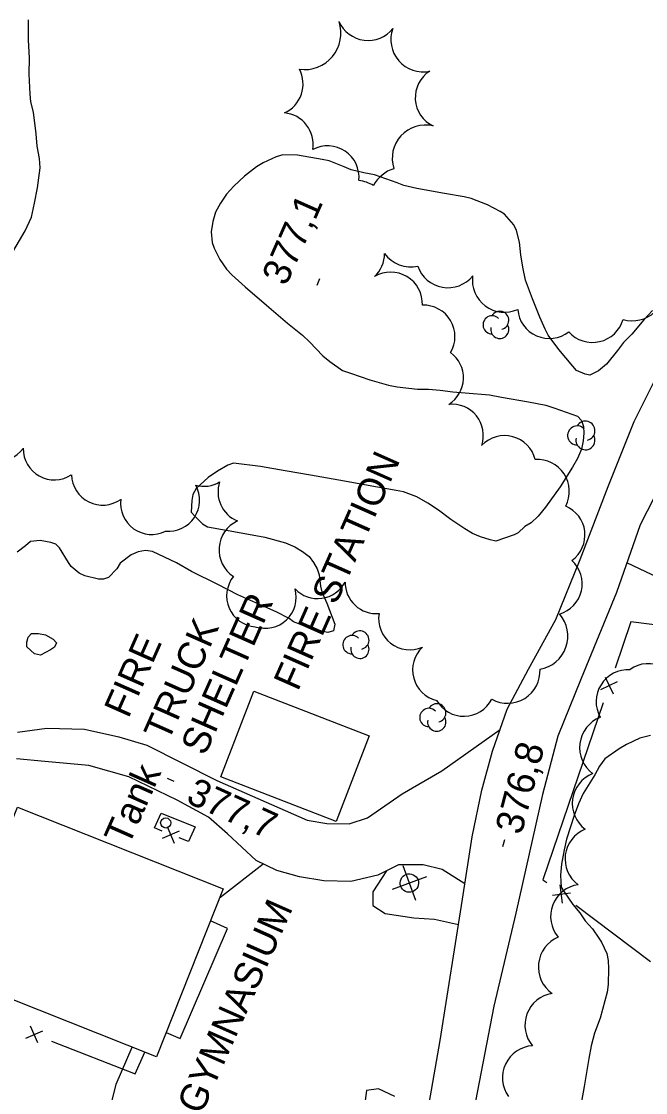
# Model space of a CAD drawing. Extents: x 287698 to 290158, y 5234163 to 5237182.
# Drawn here: x 288888.3 to 288956.3, y 5234921.6 to 5235038.1 of the extents above; entities that cross this region are included whole.
import ezdxf

# ---------------------------------------------------------------- set-up
doc = ezdxf.new("R2010")
doc.units = 0
for name, color, linetype in [('Niveau 19', 7, 'Continuous'), ('Niveau 2', 7, 'Continuous'), ('Niveau 21', 7, 'Continuous'), ('Niveau 3', 7, 'Continuous'), ('Niveau 31', 7, 'Continuous'), ('Niveau 33', 7, 'Continuous'), ('Niveau 36', 7, 'Continuous'), ('Niveau 37', 7, 'Continuous'), ('Niveau 44', 7, 'Continuous'), ('Niveau 52', 7, 'Continuous')]:
    doc.layers.add(name, color=color, linetype=linetype)

msp = doc.modelspace()

# ---------------------------------------------------------------- linework, layer by layer
at = {"layer": 'Niveau 19'}
for points in [[(288968.57, 5234988.67), (288967.38, 5234988.09), (288961.11, 5234975.94), (288954.23, 5234979.21)], [(288887.92, 5234960.79), (288891.09, 5234961.23), (288895.19, 5234961.11), (288898.95, 5234960.29), (288901.97, 5234959.39), (288909.62, 5234955.54), (288919.44, 5234951.23), (288921.59, 5234950.85), (288924.02, 5234950.81), (288925.99, 5234951.48), (288929.78, 5234954.08), (288934.08, 5234956.59), (288940.44, 5234961.08)], [(288936.59, 5234944.31), (288934.11, 5234945.84), (288932.05, 5234946.35), (288929.39, 5234946.37), (288927.14, 5234945.24), (288924.19, 5234944.55), (288921.26, 5234944.62), (288918.6, 5234945.04), (288916.14, 5234945.74), (288913.88, 5234946.83), (288910.75, 5234949.74), (288908.69, 5234951.54), (288905.3, 5234953.38), (288900.03, 5234955.94), (288895.69, 5234957.17), (288890.9, 5234957.61), (288887.82, 5234957.88)]]:
    msp.add_lwpolyline(points, dxfattribs=at)
at = {"layer": 'Niveau 2'}
for points in [[(288887.15, 5235012.59), (288888.75, 5235015.31), (288889.42, 5235016.82), (288889.78, 5235018.32), (288890.08, 5235020.01), (288890.39, 5235022.19), (288890.3, 5235023.18), (288890.07, 5235024.54), (288889.94, 5235025.86), (288889.64, 5235028.23), (288889.38, 5235029.37), (288889.3, 5235030.18), (288889.2, 5235032.37), (288889.21, 5235034.16), (288889.12, 5235036.08), (288889.1, 5235038.26)], [(288957.03, 5235006.66), (288956.09, 5235005.63), (288954.77, 5235004.09), (288953.87, 5235003.18), (288953.21, 5235002.32), (288952.02, 5235000.84), (288951.14, 5235000.1), (288950.2, 5234999.64), (288949.69, 5234999.73), (288948.73, 5235000.14), (288948.36, 5235000.61), (288946.82, 5235002.43), (288945.65, 5235003.98), (288945.33, 5235004.62), (288944.75, 5235005.94), (288943.95, 5235007.93), (288943.21, 5235009.97), (288942.89, 5235011.37), (288942.68, 5235012.72), (288942.54, 5235014.11), (288942.23, 5235015.38), (288941.93, 5235015.98), (288940.92, 5235017.14), (288940.45, 5235017.44), (288939.07, 5235018.17), (288937.3, 5235018.85), (288936.52, 5235019.01), (288934.39, 5235019.39), (288931.38, 5235019.92), (288929.94, 5235020.27), (288929.24, 5235020.56), (288926.77, 5235021.42), (288925.61, 5235021.62), (288924.24, 5235021.97), (288923.45, 5235022.27), (288921.84, 5235022.94), (288921.07, 5235023.09), (288918.39, 5235023.57), (288916.78, 5235023.61), (288916.08, 5235023.36), (288914.65, 5235022.74), (288913.93, 5235022.3), (288912.6, 5235021.26), (288911.46, 5235020.2), (288910.64, 5235019.33), (288910, 5235018.34), (288909.46, 5235017.36), (288909.18, 5235016.34), (288908.98, 5235015.23), (288909.08, 5235014.06), (288909.3, 5235013.45), (288909.93, 5235012.2), (288910.64, 5235011.16), (288911.24, 5235010.55), (288912.7, 5235009.24), (288915.01, 5235007.25), (288917.29, 5235005.3), (288918.94, 5235003.97), (288919.69, 5235003.25), (288921.14, 5235001.74), (288921.89, 5235001.1), (288923.28, 5235000.14), (288924.17, 5234999.86), (288926.27, 5234999.11), (288928.28, 5234998.53), (288929.24, 5234998.36)], [(288929.24, 5234998.36), (288931.45, 5234998.09), (288932.63, 5234998.09), (288933.91, 5234998), (288935.28, 5234997.82), (288936.62, 5234997.71), (288939.28, 5234997.48), (288940.58, 5234997.25), (288943.54, 5234996.73), (288945.4, 5234996.36), (288946.38, 5234996.03), (288948.84, 5234995.15), (288949.29, 5234994.68), (288949.5, 5234994.04), (288949.55, 5234993.3), (288949.47, 5234992.5), (288949.28, 5234991.56), (288948.87, 5234990.57), (288948.31, 5234989.62), (288946.96, 5234987.48), (288945.39, 5234985.28), (288944.59, 5234984.28), (288943.82, 5234983.58), (288943.13, 5234983.16), (288942.41, 5234982.49), (288941.96, 5234982.27), (288939.97, 5234981.58), (288939.34, 5234981.71), (288938.29, 5234982.04), (288937.44, 5234982.41), (288936.59, 5234982.91), (288935.08, 5234983.91), (288933.74, 5234984.93), (288932.58, 5234985.71), (288931.37, 5234986.39), (288929.91, 5234986.95), (288929.12, 5234987.09), (288926.09, 5234987.62), (288923.51, 5234988.08), (288919.79, 5234988.74), (288917.03, 5234989.22), (288914.37, 5234989.69), (288911.43, 5234990.05), (288910.82, 5234989.83), (288909.67, 5234989.2), (288908.66, 5234988.5), (288907.35, 5234987.29), (288907.01, 5234986.66), (288906.87, 5234986), (288906.81, 5234984.73), (288907.2, 5234984.29), (288908.05, 5234983.45), (288908.6, 5234983.13), (288909.19, 5234983.01), (288911.85, 5234982.54), (288914.82, 5234982.02), (288917.07, 5234981.4), (288918.09, 5234980.95), (288918.94, 5234980.46), (288919.65, 5234979.89), (288920.14, 5234979.25), (288920.53, 5234978.57), (288920.76, 5234977.9), (288920.87, 5234976.66), (288921.02, 5234976.05), (288921.58, 5234974.83), (288922.44, 5234972.55), (288922.29, 5234971.82), (288921.69, 5234971.65), (288921.18, 5234971.74), (288919.47, 5234972.2), (288917.95, 5234972.79), (288917.48, 5234973.14), (288916.05, 5234973.9), (288915.15, 5234974.28), (288911.89, 5234975.73), (288909.71, 5234976.84), (288906.85, 5234978.28), (288905.23, 5234979.2), (288902.61, 5234980.45), (288901.85, 5234980.55), (288901.04, 5234980.41), (288900.29, 5234980.07), (288899.09, 5234979.18), (288898.72, 5234978.56), (288897.8, 5234977.6), (288897.26, 5234977.44), (288896.74, 5234977.45), (288895.24, 5234977.81), (288894.64, 5234978.1), (288893.77, 5234978.82), (288893.48, 5234979.26), (288892.5, 5234980.83), (288892.08, 5234981.23), (288891.53, 5234981.43), (288890.37, 5234981.64), (288889.31, 5234981.52), (288888.78, 5234981.06), (288887.87, 5234980.37)], [(288889.75, 5234969.3), (288888.94, 5234970.07), (288888.94, 5234970.58), (288889.06, 5234971.12), (288889.42, 5234971.53), (288890.19, 5234971.51), (288890.95, 5234971.38), (288891.8, 5234970.9), (288892.16, 5234970.5), (288891.94, 5234970.05), (288891.5, 5234969.76), (288890.4, 5234969.18), (288889.75, 5234969.3)], [(288956.81, 5234960.43), (288955.64, 5234960.15), (288954.18, 5234959.47), (288953.38, 5234958.99), (288951.83, 5234957.88), (288951.24, 5234957.09), (288950.73, 5234956.16), (288949.46, 5234954.11), (288948.95, 5234952.98), (288948.51, 5234951.74), (288947.67, 5234949.15), (288947.4, 5234948), (288947.13, 5234946.42), (288947, 5234945.23), (288947.08, 5234943.95), (288947.41, 5234943.43), (288948.36, 5234942.04), (288949.12, 5234941.15), (288949.7, 5234940.28), (288950.5, 5234939.39), (288951.17, 5234938.38), (288951.46, 5234937.94), (288952.05, 5234936.7), (288952.2, 5234935.94), (288952.23, 5234935.08), (288952.19, 5234933.34), (288952.07, 5234932.53)], [(288952.07, 5234932.53), (288951.31, 5234929.7), (288950.71, 5234928.06), (288950.35, 5234926.68), (288950.1, 5234925.28), (288949.57, 5234922.25), (288949.1, 5234919.61)]]:
    msp.add_lwpolyline(points, dxfattribs=at)
at = {"layer": 'Niveau 21'}
for points in [[(288922.94, 5234844.51), (288923.87, 5234858.3), (288925.42, 5234875.13), (288927.29, 5234887.83), (288929.11, 5234901.59), (288931.93, 5234915.83), (288933.92, 5234927.24), (288936.33, 5234942.64), (288937.38, 5234949.4), (288938.45, 5234954.47), (288939.61, 5234958.71), (288941.21, 5234963.3), (288943.54, 5234967.66), (288946.48, 5234973.06), (288949.16, 5234979.57), (288952.18, 5234987.51), (288955.03, 5234994.58), (288959.1, 5235002.7)], [(288959.42, 5234990.64), (288955.67, 5234983.34), (288953.1, 5234975.97), (288949.25, 5234966.62), (288946.73, 5234960.36), (288945.04, 5234954), (288942.16, 5234941.12), (288939.76, 5234930.98), (288935.54, 5234909.21), (288933.35, 5234897.51), (288931.99, 5234888.65), (288930.97, 5234880.34), (288929.91, 5234871.55), (288929.29, 5234862.75), (288928.74, 5234854.31)]]:
    msp.add_lwpolyline(points, dxfattribs=at)
at = {"layer": 'Niveau 3'}
for p, q in [((288920.51, 5235009.4), (288920.83, 5235010.13)), ((288904.19, 5234955.79), (288904.91, 5234955.45)), ((288940.72, 5234948.35), (288940.96, 5234949.11))]:
    msp.add_line(p, q, dxfattribs=at)
at = {"layer": 'Niveau 31'}
for points in [[(288922.58, 5234951.08), (288910.05, 5234955.93), (288913.65, 5234965.24), (288926.18, 5234960.39)], [(288887.92, 5234952.65), (288910.3, 5234943.77), (288903.05, 5234925.48), (288880.66, 5234934.36)]]:
    msp.add_lwpolyline(points, close=True, dxfattribs=at)
at = {"layer": 'Niveau 33'}
msp.add_circle((288904.04, 5234950.92), 0.553, dxfattribs=at)
at = {"layer": 'Niveau 36'}
for p, q in [((288931.25, 5234942.5), (288929.88, 5234946.25)), ((288932.44, 5234945.06), (288928.69, 5234943.69))]:
    msp.add_line(p, q, dxfattribs=at)
msp.add_ellipse((288930.56, 5234944.38), major_axis=(-0.907, 0.42), ratio=0.999982, dxfattribs=at)
at = {"layer": 'Niveau 37'}
for p, q in [((288951.41, 5234965.43), (288953.21, 5234966.31)), ((288951.87, 5234966.77), (288952.75, 5234964.96)), ((288951.66, 5234963.98), (288945.07, 5234944.73)), ((288905.51, 5234950.03), (288903.66, 5234949.24)), ((288904.2, 5234950.55), (288904.98, 5234948.71)), ((288945.07, 5234944.73), (288945.52, 5234944.43)), ((288947.23, 5234942.21), (288946.98, 5234944.2)), ((288946.12, 5234943.07), (288948.1, 5234943.32)), ((288948.69, 5234941.97), (288956.81, 5234935.83)), ((288888.82, 5234927.5), (288890.66, 5234928.3)), ((288890.14, 5234926.99), (288889.33, 5234928.82))]:
    msp.add_line(p, q, dxfattribs=at)
for points in [[(288960.36, 5234972.06), (288954.65, 5234972.79), (288952.96, 5234967.76)], [(288902.82, 5234950.37), (288903.56, 5234951.97), (288907.24, 5234950.48)], [(288903.65, 5234950.04), (288902.82, 5234950.37)], [(288907.24, 5234950.48), (288906.51, 5234948.89), (288905.51, 5234949.29)], [(288891.6, 5234927.18), (288900.72, 5234923.62), (288901.77, 5234925.99)]]:
    msp.add_lwpolyline(points, dxfattribs=at)
at = {"layer": 'Niveau 44'}
for centre, radius, start, end in [((288934.62, 5235029.82), 3.42, 122.6471, 244.4458), ((288932.11, 5235003.83), 3.41, 329.0542, 92.1192), ((288939.56, 5235005.1), 0.984, 44.1154, 269.804), ((288940.4, 5235005.59), 0.984, 282.2692, 149.7263), ((288940.4, 5235004.6), 0.984, 166.9369, 29.6212), ((288949.72, 5234993.59), 1.04, 282.2692, 149.7263), ((288940.92, 5234989.61), 3.44, 14.1763, 136.1328), ((288948.82, 5234993.07), 1.04, 44.1154, 269.804), ((288949.72, 5234992.55), 1.04, 166.9369, 29.6212), ((288944.5, 5234986.99), 3.47, 332.3373, 94.0989), ((288897.18, 5234988.9), 3.41, 182.1987, 305.2703), ((288946.28, 5234982.24), 3.39, 305.5095, 67.6396), ((288945.94, 5234976.94), 3.43, 286.0359, 47.7022), ((288914.06, 5234975.63), 3.39, 141.6594, 265.3912), ((288920.57, 5234978.74), 3.41, 223.9818, 331.7705), ((288926.96, 5234977.08), 3.39, 179.2037, 275.0598), ((288930.6, 5234973.14), 3.39, 170.3322, 294.0521), ((288944.15, 5234971.24), 3.65, 279.7592, 41.3208), ((288924.31, 5234970.31), 0.997, 44.1154, 269.804), ((288925.17, 5234970.81), 0.997, 282.2692, 149.7263), ((288925.17, 5234969.81), 0.997, 166.9369, 29.6212), ((288941.24, 5234967.47), 3.54, 240.9182, 2.9158), ((288933.54, 5234962.89), 0.997, 282.2692, 149.7263), ((288936.49, 5234965.92), 3.4, 209.3941, 333.0924), ((288932.68, 5234962.39), 0.997, 44.1154, 269.804), ((288933.54, 5234961.89), 0.997, 166.9369, 29.6212), ((288951.78, 5234953.03), 3.49, 111.3196, 233.243), ((288948.13, 5234935.25), 3.53, 113.0019, 234.7077)]:
    msp.add_arc(centre, radius, start, end, dxfattribs=at)
for centre, major_axis, ratio, start_param, end_param in [((288919.16, 5235036.82), (3.14, -2.4), 0.999996, 5.219897, 7.261747), ((288926.06, 5235039.46), (3.4, -0.61), 0.991209, 3.732573, 5.789598), ((288932.05, 5235036.13), (-2.66, -2.29), 0.999995, 5.222982, 7.349443), ((288915.56, 5235031.28), (1.91, 2.87), 0.993247, 4.149687, 5.78893), ((288916.66, 5235024.74), (-2.73, 2.09), 0.995612, 3.632355, 5.277877), ((288932.3, 5235023.23), (-2.41, 2.68), 0.999633, 5.315611, 7.443684), ((288921.66, 5235021.15), (-2.85, 1.92), 0.995077, 3.632778, 5.792), ((288929.98, 5235018.51), (-3.66, 0.79), 0.999532, 5.223442, 6.013661), ((288924.59, 5235016.81), (3.79, 1.32), 0.999021, 0.694742, 1.113562), ((288924.4, 5235012.86), (3.45, 0.22), 0.99983, 5.403924, 6.220617), ((288930.69, 5235014.84), (3.28, -1.08), 0.998256, 4.068871, 5.262004), ((288928.54, 5235007.4), (-2.96, 1.77), 0.994489, 3.634964, 5.789814), ((288934.75, 5235012.55), (3.39, -0.6), 0.991134, 3.637315, 5.787463), ((288940.91, 5235009.96), (-2.08, -2.81), 0.999979, 5.216444, 7.344238), ((288954.87, 5235008.95), (3.23, 1.18), 0.991049, 4.054825, 6.209846), ((288945.78, 5235007.04), (3.16, -1.38), 0.993265, 3.63487, 5.789908), ((288950.5, 5235006.6), (3.36, 0.77), 0.990381, 3.636849, 5.787929), ((288933.05, 5234999.33), (3.38, -0.33), 0.999384, 5.367059, 7.32689), ((288935.22, 5234993.07), (2.83, 1.87), 0.999757, 5.374364, 7.381812), ((288885.78, 5234993.68), (3.37, -0.47), 0.999984, 3.636088, 5.78869), ((288891.93, 5234991.64), (-1.78, -2.9), 0.999548, 5.254426, 7.405499), ((288904.33, 5234986.03), (1.87, 2.83), 0.999984, 3.632717, 5.792061), ((288908.17, 5234990.92), (2.38, -2.41), 0.999641, 5.248673, 6.042891), ((288913.13, 5234986.92), (0.36, -3.38), 0.999984, 4.276966, 5.79017), ((288902.51, 5234985.69), (-1.93, -2.79), 0.998826, 5.189568, 7.349758), ((288913.3, 5234980.63), (-3.45, 0.26), 0.99965, 5.220646, 7.348566), ((288914.85, 5234975.48), (2.46, 2.34), 0.999984, 3.6345, 5.790278), ((288934.32, 5234967.56), (0.88, -3.29), 0.999984, 3.636329, 5.788449), ((288954.35, 5234964.11), (0.22, -3.46), 0.999609, 3.011534, 5.162366), ((288956.58, 5234964.78), (-0.59, 3.42), 0.999534, 4.570625, 6.723711), ((288952.62, 5234959.11), (2.82, -2.13), 0.999984, 2.59332, 4.720052), ((288950.98, 5234947), (-3.45, 0.44), 0.999913, 5.218271, 7.346261), ((288949.42, 5234940.75), (-3.26, 1.25), 0.999737, 5.221542, 7.347251), ((288946.61, 5234928.93), (-3.26, 1.21), 0.999951, 5.218299, 7.345954), ((288944.18, 5234923.2), (2, -2.86), 0.999984, 2.594488, 4.7227)]:
    msp.add_ellipse(centre, major_axis=major_axis, ratio=ratio, start_param=start_param, end_param=end_param, dxfattribs=at)
at = {"layer": 'Niveau 52'}
for points in [[(288909.9, 5234942.76), (288914.64, 5234946.46)], [(288928.08, 5234945.71), (288926.57, 5234943.41), (288926.58, 5234941.95), (288927.93, 5234941.08), (288931.03, 5234940.58), (288933.3, 5234940.46), (288935.9, 5234939.87)], [(288904.09, 5234928.11), (288905.61, 5234927.46), (288910.75, 5234939.45), (288908.91, 5234940.27)], [(288898.01, 5234919.86), (288898.66, 5234922.49), (288900.39, 5234926.54)], [(288928.99, 5234921.15), (288927.19, 5234921.99), (288925.9, 5234921.83), (288925.75, 5234920.74)]]:
    msp.add_lwpolyline(points, dxfattribs=at)

# ---------------------------------------------------------------- texts
at = {"layer": 'Niveau 3'}
for s, rotation, p in [('377,1', 66.1217, (288917.14, 5235009.22)), ('376,8', 75.3015, (288942.75, 5234949.53)), ('377,7', 335.6102, (288906.12, 5234953.21))]:
    msp.add_text(s, height=3, rotation=rotation, dxfattribs=at).set_placement(p)
at = {"layer": 'Niveau 31'}
for s, p in [('FIRE STATION', (288918.42, 5234965.15)), ('SHELTER', (288908.32, 5234958.11)), ('TRUCK', (288904.3, 5234959.62)), ('FIRE', (288899.98, 5234962.2)), ('GYMNASIUM', (288907.92, 5234919.07))]:
    msp.add_text(s, height=3, rotation=66.1212, dxfattribs=at).set_placement(p)
at = {"layer": 'Niveau 33'}
msp.add_text('Tank', height=3, rotation=66.1217, dxfattribs=at).set_placement((288899.99, 5234948.28))

doc.saveas('drawing.dxf')
